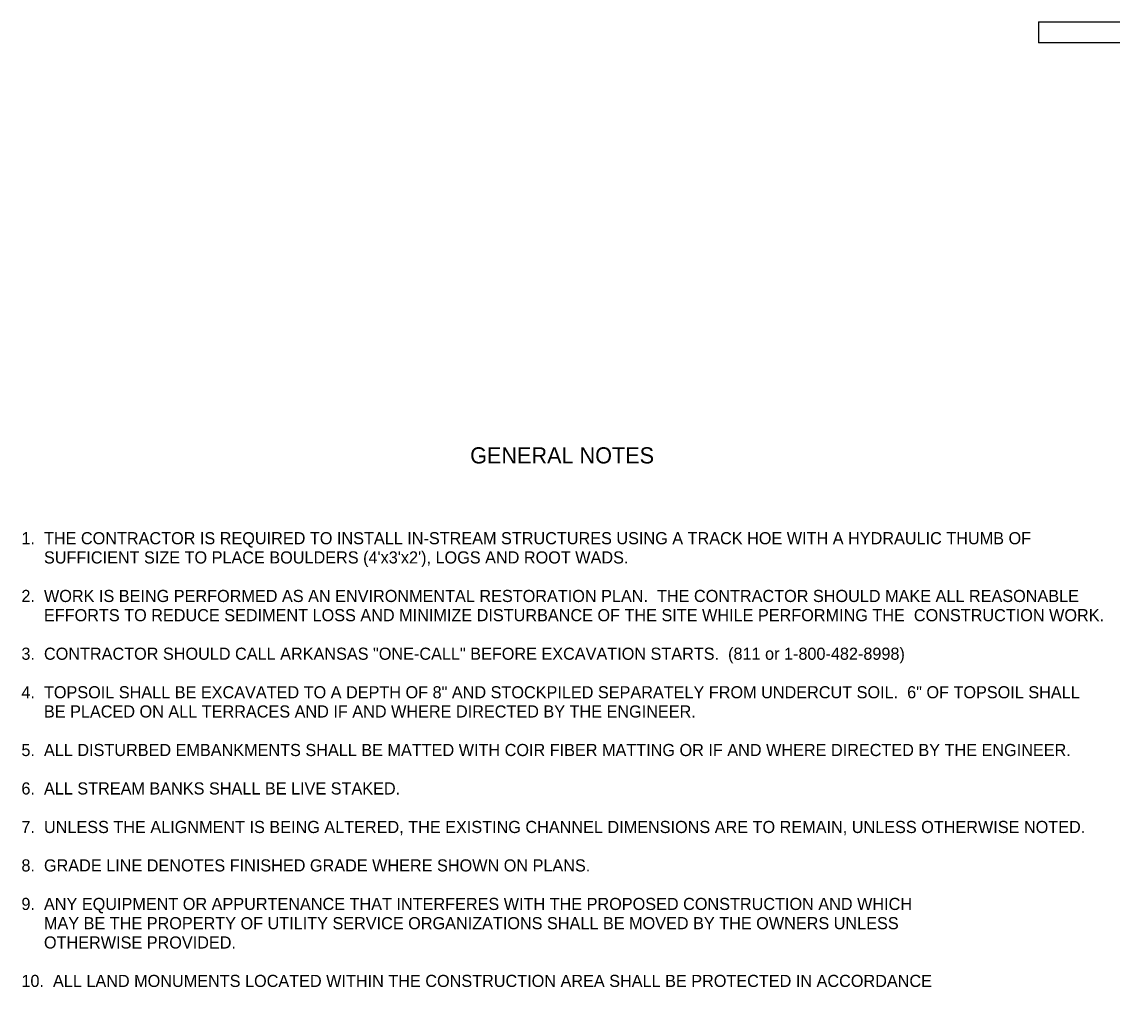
# Model space of a CAD drawing. Extents: x 1955708 to 1956002, y 566396 to 566594.
# Drawn here: x 1955839.3 to 1955947.1, y 566496.6 to 566592.1 of the extents above; entities that cross this region are included whole.
import ezdxf

# ---------------------------------------------------------------- set-up
doc = ezdxf.new("R2010")
doc.units = 0
for name, color, linetype in [('Old_Level_1', 7, 'Continuous'), ('Old_Level_44', 7, 'Continuous'), ('R_Border', 7, 'Continuous')]:
    doc.layers.add(name, color=color, linetype=linetype)

msp = doc.modelspace()

# ---------------------------------------------------------------- linework, layer by layer
at = {"layer": 'R_Border'}
for p, q in [((1955939.81, 566592.09), (1955959.26, 566592.09)), ((1955939.81, 566592.09), (1955939.81, 566590.03)), ((1956002.36, 566590.03), (1955939.81, 566590.03))]:
    msp.add_line(p, q, dxfattribs=at)

# ---------------------------------------------------------------- texts
at = {"layer": 'Old_Level_1'}
for s, p in [('1.  THE CONTRACTOR IS REQUIRED TO INSTALL IN-STREAM STRUCTURES USING A TRACK HOE WITH A HYDRAULIC THUMB OF', (1955839.23, 566540.44)), ("     SUFFICIENT SIZE TO PLACE BOULDERS (4'x3'x2'), LOGS AND ROOT WADS.", (1955839.23, 566538.54)), ('2.  WORK IS BEING PERFORMED AS AN ENVIRONMENTAL RESTORATION PLAN.  THE CONTRACTOR SHOULD MAKE ALL REASONABLE', (1955839.23, 566534.73)), ('     EFFORTS TO REDUCE SEDIMENT LOSS AND MINIMIZE DISTURBANCE OF THE SITE WHILE PERFORMING THE  CONSTRUCTION WORK.', (1955839.23, 566532.83)), ('3.  CONTRACTOR SHOULD CALL ARKANSAS "ONE-CALL" BEFORE EXCAVATION STARTS.  (811 or 1-800-482-8998)', (1955839.23, 566529.02)), ('4.  TOPSOIL SHALL BE EXCAVATED TO A DEPTH OF 8" AND STOCKPILED SEPARATELY FROM UNDERCUT SOIL.  6" OF TOPSOIL SHALL', (1955839.23, 566525.21)), ('     BE PLACED ON ALL TERRACES AND IF AND WHERE DIRECTED BY THE ENGINEER.', (1955839.23, 566523.31)), ('5.  ALL DISTURBED EMBANKMENTS SHALL BE MATTED WITH COIR FIBER MATTING OR IF AND WHERE DIRECTED BY THE ENGINEER.', (1955839.23, 566519.5)), ('6.  ALL STREAM BANKS SHALL BE LIVE STAKED.', (1955839.23, 566515.7)), ('7.  UNLESS THE ALIGNMENT IS BEING ALTERED, THE EXISTING CHANNEL DIMENSIONS ARE TO REMAIN, UNLESS OTHERWISE NOTED.', (1955839.23, 566511.89)), ('8.  GRADE LINE DENOTES FINISHED GRADE WHERE SHOWN ON PLANS.', (1955839.23, 566508.09)), ('9.  ANY EQUIPMENT OR APPURTENANCE THAT INTERFERES WITH THE PROPOSED CONSTRUCTION AND WHICH', (1955839.23, 566504.28)), ('     MAY BE THE PROPERTY OF UTILITY SERVICE ORGANIZATIONS SHALL BE MOVED BY THE OWNERS UNLESS', (1955839.23, 566502.38)), ('     OTHERWISE PROVIDED.', (1955839.23, 566500.47)), ('10.  ALL LAND MONUMENTS LOCATED WITHIN THE CONSTRUCTION AREA SHALL BE PROTECTED IN ACCORDANCE', (1955839.23, 566496.67))]:
    msp.add_text(s, height=1.2, dxfattribs=at).set_placement(p)
at = {"layer": 'Old_Level_44'}
msp.add_text('GENERAL NOTES', height=1.6, dxfattribs=at).set_placement((1955883.61, 566548.43))

doc.saveas('drawing.dxf')
